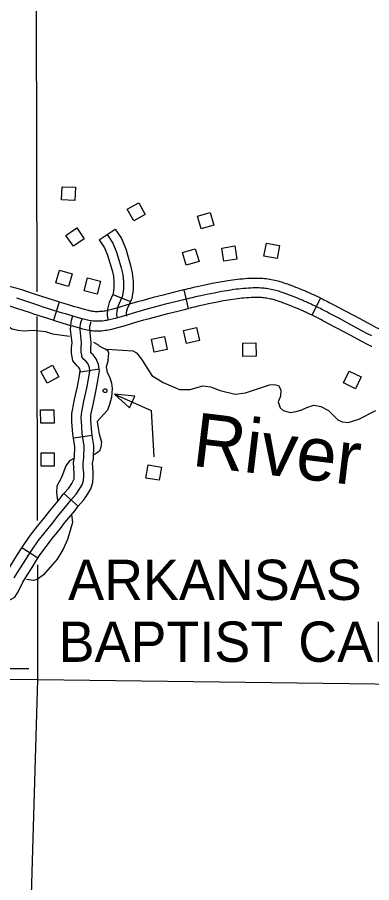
# Model space of a CAD drawing. Extents: x -19 to 366, y -4 to 359.
# Drawn here: x 137.366 to 137.894, y 192.721 to 194.009 of the extents above; entities that cross this region are included whole.
import ezdxf

# ---------------------------------------------------------------- set-up
doc = ezdxf.new("R2010")
doc.units = 0
for name, color, linetype in [('21', 7, 'Continuous'), ('60', 7, 'Continuous'), ('R_Axis Annot', 7, 'Continuous'), ('R_ROW', 7, 'Continuous'), ('R_ROW Annot', 7, 'Continuous'), ('R_Temp Easement', 7, 'Continuous'), ('Sheet Fence', 7, 'Continuous')]:
    doc.layers.add(name, color=color, linetype=linetype)

msp = doc.modelspace()

# ---------------------------------------------------------------- linework, layer by layer
at = {"layer": '21'}
for points in [[(137.4528, 193.7563), (137.452, 193.7366), (137.4322, 193.7374), (137.4331, 193.7571)], [(137.5395, 193.7062), (137.5299, 193.7234), (137.5472, 193.733), (137.5568, 193.7158)], [(137.6533, 193.7189), (137.6589, 193.7), (137.6399, 193.6944), (137.6343, 193.7133)], [(137.4548, 193.6958), (137.466, 193.6796), (137.4498, 193.6683), (137.4386, 193.6845)], [(137.6902, 193.6688), (137.6932, 193.6493), (137.6737, 193.6463), (137.6706, 193.6657)], [(137.7564, 193.6696), (137.7529, 193.6502), (137.7334, 193.6538), (137.737, 193.6732)], [(137.6312, 193.6648), (137.6368, 193.6459), (137.6178, 193.6403), (137.6122, 193.6592)], [(137.4234, 193.6141), (137.4291, 193.633), (137.448, 193.6272), (137.4423, 193.6084)], [(137.49, 193.6164), (137.485, 193.5973), (137.4659, 193.6022), (137.4708, 193.6213)], [(137.6375, 193.5283), (137.6183, 193.5237), (137.6137, 193.5429), (137.6329, 193.5476)], [(137.5699, 193.5108), (137.566, 193.5302), (137.5854, 193.5341), (137.5893, 193.5148)], [(137.702, 193.5043), (137.7017, 193.524), (137.7214, 193.5244), (137.7218, 193.5047)], [(137.4279, 193.4738), (137.4105, 193.4645), (137.4012, 193.482), (137.4185, 193.4913)], [(137.8782, 193.4741), (137.8697, 193.4563), (137.8518, 193.4648), (137.8604, 193.4826)], [(137.5332, 193.4278), (137.5411, 193.4454), (137.5108, 193.4484)], [(137.4012, 193.4049), (137.4009, 193.4246), (137.4206, 193.425), (137.421, 193.4052)], [(137.4016, 193.3411), (137.4016, 193.3608), (137.4213, 193.3608), (137.4213, 193.3411)], [(137.5578, 193.3233), (137.5612, 193.3427), (137.5807, 193.3393), (137.5773, 193.3199)]]:
    msp.add_lwpolyline(points, close=True, dxfattribs=at)
msp.add_lwpolyline([(137.5108, 193.4484), (137.5653, 193.424), (137.5693, 193.355)], dxfattribs=at)
msp.add_circle((137.4969, 193.4533), 0.00284, dxfattribs=at)
at = {"layer": '60'}
msp.add_line((137.2746, 193.0395), (137.3833, 193.0395), dxfattribs=at)
at = {"layer": 'R_Axis Annot'}
for points in [[(137.3958, 193.6004), (137.395, 194.0184)], [(137.3965, 193.2601), (137.3959, 193.5638)], [(137.3969, 193.0228), (137.3966, 193.1939)], [(137.3969, 193.0228), (137.0833, 193.0239)], [(137.3674, 192.0278), (137.3969, 193.0228)], [(138.4006, 193.0099), (137.3969, 193.0228)]]:
    msp.add_lwpolyline(points, dxfattribs=at)
at = {"layer": 'R_ROW'}
for p, q in [((137.6212, 193.5759), (137.6146, 193.6035)), ((137.8052, 193.5656), (137.8174, 193.5913)), ((137.8174, 193.5913), (137.8174, 193.5913)), ((137.4284, 193.5854), (137.42, 193.5582)), ((137.5174, 193.5773), (137.5174, 193.5773))]:
    msp.add_line(p, q, dxfattribs=at)
for points in [[(137.7159, 193.6205), (137.7134, 193.6204), (137.7093, 193.6202), (137.7053, 193.6199), (137.7014, 193.6196), (137.6977, 193.6192), (137.694, 193.6188), (137.6903, 193.6184), (137.6866, 193.6178), (137.6794, 193.6167), (137.6684, 193.615), (137.6564, 193.6127), (137.6452, 193.6105), (137.6362, 193.6085), (137.6284, 193.6068), (137.6233, 193.6055), (137.6202, 193.6048), (137.6169, 193.6041), (137.6146, 193.6035)], [(137.8174, 193.5913), (137.8171, 193.5914), (137.8114, 193.5941), (137.8095, 193.595), (137.8076, 193.5959), (137.8056, 193.5968), (137.8037, 193.5977), (137.8018, 193.5985), (137.7999, 193.5993), (137.7979, 193.6002), (137.796, 193.601), (137.7941, 193.6018), (137.7896, 193.6036), (137.7851, 193.6055), (137.783, 193.6063), (137.781, 193.6072), (137.779, 193.608), (137.7769, 193.6088), (137.7749, 193.6095), (137.7729, 193.6103), (137.7708, 193.6111), (137.7687, 193.6118), (137.7666, 193.6125), (137.7621, 193.614), (137.7598, 193.6148), (137.7573, 193.6156), (137.7547, 193.6163), (137.7521, 193.617), (137.7495, 193.6176), (137.7469, 193.6181), (137.7418, 193.619), (137.7394, 193.6194), (137.7369, 193.6198), (137.7343, 193.6201), (137.7317, 193.6203), (137.7292, 193.6204), (137.7266, 193.6205), (137.7169, 193.6205), (137.7159, 193.6205)], [(137.4284, 193.5854), (137.428, 193.5855), (137.4233, 193.587), (137.4186, 193.5885), (137.4138, 193.59), (137.4092, 193.5915), (137.4044, 193.593), (137.3997, 193.5945), (137.395, 193.5961), (137.3731, 193.6034), (137.3695, 193.6045), (137.3659, 193.6056), (137.3623, 193.6066), (137.3587, 193.6076), (137.355, 193.6085), (137.3513, 193.6093), (137.3477, 193.61), (137.344, 193.6107), (137.3402, 193.6114), (137.3365, 193.612), (137.3328, 193.6125), (137.3297, 193.6128)], [(137.8939, 193.5348), (137.8866, 193.5387), (137.8617, 193.552), (137.8456, 193.5606), (137.8299, 193.569), (137.8278, 193.5701), (137.8258, 193.5712), (137.8237, 193.5723), (137.8216, 193.5734), (137.8195, 193.5744), (137.8174, 193.5755), (137.8153, 193.5765), (137.8132, 193.5776), (137.811, 193.5786), (137.8053, 193.5813), (137.8035, 193.5822), (137.8016, 193.583), (137.7998, 193.5839), (137.798, 193.5847), (137.7961, 193.5855), (137.7943, 193.5863), (137.7924, 193.5871), (137.7906, 193.5879), (137.7887, 193.5886), (137.7841, 193.5905), (137.7796, 193.5924), (137.7777, 193.5932), (137.7757, 193.594), (137.7738, 193.5947), (137.7718, 193.5955), (137.7699, 193.5962), (137.7679, 193.597), (137.766, 193.5977), (137.764, 193.5984), (137.762, 193.5991), (137.7576, 193.6006), (137.7554, 193.6013), (137.7532, 193.602), (137.751, 193.6026), (137.7487, 193.6032), (137.7465, 193.6037), (137.7443, 193.6042), (137.7394, 193.605), (137.7373, 193.6054), (137.7351, 193.6057), (137.733, 193.6059), (137.7308, 193.6061), (137.7286, 193.6062), (137.7264, 193.6063), (137.7171, 193.6063), (137.714, 193.6062), (137.7102, 193.606), (137.7063, 193.6057), (137.7027, 193.6054), (137.6992, 193.6051), (137.6957, 193.6047), (137.6922, 193.6043), (137.6887, 193.6038), (137.6815, 193.6027), (137.6709, 193.601), (137.6591, 193.5988), (137.6481, 193.5966), (137.6393, 193.5946), (137.6316, 193.5929), (137.6265, 193.5917), (137.6234, 193.591), (137.6201, 193.5902), (137.6169, 193.5895), (137.6137, 193.5887), (137.6018, 193.5858), (137.5868, 193.582), (137.5721, 193.5782), (137.5554, 193.5735), (137.5508, 193.5723), (137.5386, 193.5688), (137.5241, 193.5645), (137.5121, 193.561), (137.5037, 193.5588), (137.5017, 193.5584), (137.4997, 193.558)], [(137.6146, 193.6035), (137.6136, 193.6033), (137.6103, 193.6025), (137.5983, 193.5995), (137.5833, 193.5958), (137.5684, 193.5919), (137.5516, 193.5872), (137.5469, 193.586), (137.5347, 193.5825), (137.5201, 193.5781), (137.5174, 193.5773)], [(137.4627, 193.5604), (137.4573, 193.562), (137.4525, 193.5633), (137.4477, 193.5647), (137.4429, 193.5662), (137.4381, 193.5676), (137.4334, 193.569), (137.4286, 193.5705), (137.4238, 193.5719), (137.419, 193.5734), (137.4143, 193.5749), (137.4095, 193.5764), (137.4048, 193.5779), (137.4, 193.5795), (137.3953, 193.581), (137.3906, 193.5826), (137.3687, 193.5899), (137.3654, 193.5909)], [(137.7169, 193.5921), (137.7146, 193.592), (137.711, 193.5918), (137.7074, 193.5916), (137.7039, 193.5913), (137.7006, 193.591), (137.6973, 193.5906), (137.6941, 193.5902), (137.6908, 193.5897), (137.6837, 193.5886), (137.6733, 193.587), (137.6618, 193.5848), (137.651, 193.5827), (137.6423, 193.5808), (137.6348, 193.5791), (137.6298, 193.5779), (137.6266, 193.5772), (137.6234, 193.5764), (137.6212, 193.5759)], [(137.8052, 193.5656), (137.805, 193.5657), (137.7992, 193.5685), (137.7974, 193.5693), (137.7957, 193.5701), (137.7939, 193.5709), (137.7922, 193.5717), (137.7904, 193.5725), (137.7887, 193.5732), (137.7869, 193.574), (137.7852, 193.5747), (137.7833, 193.5755), (137.7787, 193.5774), (137.7742, 193.5793), (137.7723, 193.58), (137.7704, 193.5808), (137.7686, 193.5815), (137.7668, 193.5822), (137.7649, 193.5829), (137.763, 193.5836), (137.7612, 193.5843), (137.7593, 193.585), (137.7574, 193.5856), (137.753, 193.5871), (137.751, 193.5878), (137.7491, 193.5884), (137.7473, 193.5889), (137.7454, 193.5894), (137.7435, 193.5898), (137.7416, 193.5902), (137.7371, 193.591), (137.7352, 193.5913), (137.7334, 193.5916), (137.7316, 193.5918), (137.7298, 193.5919), (137.7281, 193.592), (137.7262, 193.5921), (137.7174, 193.5921), (137.7169, 193.5921)], [(137.8174, 193.5913), (137.8193, 193.5904), (137.8215, 193.5893), (137.8237, 193.5882), (137.8259, 193.5871), (137.8281, 193.586), (137.8302, 193.5849), (137.8324, 193.5838), (137.8346, 193.5826), (137.8366, 193.5815), (137.8523, 193.5731), (137.8684, 193.5646), (137.8933, 193.5512), (137.9003, 193.5474), (137.903, 193.5462), (137.9058, 193.5448), (137.9059, 193.5448)], [(137.42, 193.5582), (137.4196, 193.5584), (137.4148, 193.5599), (137.41, 193.5614), (137.4052, 193.5629), (137.4004, 193.5644), (137.3956, 193.566), (137.3909, 193.5675), (137.3861, 193.5691), (137.3643, 193.5764), (137.3612, 193.5774), (137.358, 193.5783), (137.3549, 193.5792), (137.3517, 193.58), (137.3485, 193.5808), (137.3453, 193.5815), (137.3421, 193.5822), (137.3389, 193.5828), (137.3357, 193.5833), (137.3324, 193.5838), (137.3293, 193.5843), (137.3265, 193.5846)], [(137.5174, 193.5773), (137.5084, 193.5747), (137.5004, 193.5726), (137.4988, 193.5723), (137.4972, 193.572), (137.4956, 193.5717), (137.4937, 193.5715), (137.4915, 193.5713), (137.4893, 193.5711), (137.4871, 193.5709), (137.4852, 193.5709), (137.4838, 193.5709), (137.4821, 193.571), (137.4804, 193.5711), (137.4787, 193.5713), (137.477, 193.5716), (137.4755, 193.5718), (137.4704, 193.573), (137.4665, 193.5741), (137.4612, 193.5756), (137.4565, 193.577), (137.4517, 193.5784), (137.447, 193.5798), (137.4422, 193.5812), (137.4375, 193.5826), (137.4327, 193.5841), (137.4284, 193.5854)], [(137.5253, 193.55), (137.5282, 193.5508), (137.5426, 193.5552), (137.5546, 193.5586), (137.5591, 193.5598), (137.5758, 193.5644), (137.5903, 193.5682), (137.6052, 193.572), (137.6171, 193.5749), (137.6203, 193.5757), (137.6212, 193.5759)], [(137.8937, 193.5191), (137.8936, 193.5192), (137.8906, 193.5206), (137.8875, 193.5221), (137.8799, 193.5261), (137.855, 193.5395), (137.8389, 193.5481), (137.8232, 193.5565), (137.8211, 193.5576), (137.8191, 193.5586), (137.8171, 193.5597), (137.8151, 193.5607), (137.8131, 193.5618), (137.8111, 193.5628), (137.809, 193.5638), (137.807, 193.5648), (137.8052, 193.5656)], [(137.42, 193.5582), (137.4244, 193.5569), (137.4293, 193.5554), (137.4341, 193.554), (137.4389, 193.5525), (137.4437, 193.5511), (137.4485, 193.5497), (137.4534, 193.5483), (137.4588, 193.5468), (137.4634, 193.5455), (137.47, 193.544), (137.4726, 193.5435), (137.4751, 193.5432), (137.4776, 193.5429), (137.4801, 193.5427), (137.4826, 193.5425), (137.4853, 193.5424), (137.4885, 193.5426), (137.4914, 193.5427), (137.4942, 193.543), (137.4971, 193.5433), (137.4997, 193.5436), (137.5021, 193.544), (137.5046, 193.5445), (137.5069, 193.545), (137.5158, 193.5473), (137.5253, 193.55)], [(137.4997, 193.558), (137.4977, 193.5577), (137.4954, 193.5574), (137.4929, 193.5571), (137.4904, 193.5569), (137.4878, 193.5567), (137.4853, 193.5567), (137.4832, 193.5567), (137.4811, 193.5568), (137.479, 193.557), (137.4769, 193.5572), (137.4748, 193.5575), (137.4728, 193.5579), (137.4669, 193.5592), (137.4627, 193.5604)]]:
    msp.add_lwpolyline(points, dxfattribs=at)
at = {"layer": 'R_ROW Annot'}
for p, q in [((137.4882, 193.6781), (137.5118, 193.6939)), ((137.5083, 193.5968), (137.5345, 193.5859)), ((137.4883, 193.4855), (137.4602, 193.4809)), ((137.4779, 193.3867), (137.4498, 193.3825)), ((137.4568, 193.2813), (137.4356, 193.3002)), ((137.3968, 193.2038), (137.3732, 193.2196))]:
    msp.add_line(p, q, dxfattribs=at)
for points in [[(137.5118, 193.6939), (137.5212, 193.6798), (137.5276, 193.6645), (137.5346, 193.6398), (137.5374, 193.6286), (137.5385, 193.6161), (137.5385, 193.604), (137.5365, 193.5907), (137.5345, 193.5859)], [(137.5, 193.686), (137.5086, 193.673), (137.5141, 193.6598), (137.5209, 193.6361), (137.5234, 193.6262), (137.5243, 193.6155), (137.5243, 193.605), (137.5227, 193.5945), (137.5166, 193.5797), (137.5144, 193.5724), (137.5141, 193.5665), (137.515, 193.5618)], [(137.4882, 193.6781), (137.496, 193.6663), (137.5007, 193.6551), (137.5072, 193.6324), (137.5093, 193.6239), (137.5101, 193.6149), (137.5101, 193.606), (137.5089, 193.5984), (137.5083, 193.5968)], [(137.5083, 193.5968), (137.5032, 193.5845), (137.5003, 193.5748), (137.4999, 193.5656), (137.501, 193.5593)], [(137.5345, 193.5859), (137.53, 193.575), (137.5285, 193.57), (137.5284, 193.5674), (137.529, 193.5644)], [(137.4602, 193.4809), (137.4597, 193.484), (137.4586, 193.4866), (137.4577, 193.4879), (137.4552, 193.4902), (137.4488, 193.4976), (137.448, 193.504), (137.4471, 193.5093), (137.4471, 193.5176), (137.4477, 193.5244), (137.4456, 193.5438), (137.4457, 193.5504), (137.447, 193.5583), (137.4491, 193.5648)], [(137.3618, 193.1749), (137.3691, 193.1865), (137.3764, 193.1978), (137.383, 193.2086), (137.3878, 193.2158), (137.3975, 193.2297), (137.4075, 193.2427), (137.4191, 193.2567), (137.426, 193.2659), (137.4407, 193.2835), (137.4457, 193.2902), (137.454, 193.2995), (137.4593, 193.3075), (137.4626, 193.3131), (137.4647, 193.3194), (137.4652, 193.3259), (137.4651, 193.3303), (137.4645, 193.3397), (137.4641, 193.3457), (137.4655, 193.3532), (137.4659, 193.3707), (137.463, 193.39), (137.4616, 193.4079), (137.4614, 193.4129), (137.4617, 193.4178), (137.4623, 193.4217), (137.4655, 193.4375), (137.4696, 193.4571), (137.4725, 193.4736), (137.4743, 193.4829), (137.4735, 193.488), (137.471, 193.4937), (137.4684, 193.4973), (137.4655, 193.5), (137.4624, 193.5036), (137.4621, 193.5062), (137.4613, 193.5105), (137.4613, 193.517), (137.4619, 193.5246), (137.4598, 193.5445), (137.4599, 193.5491), (137.4609, 193.5549), (137.4627, 193.5604)], [(137.4883, 193.4855), (137.4872, 193.4921), (137.4834, 193.5008), (137.4791, 193.5068), (137.4759, 193.5098), (137.4755, 193.5118), (137.4755, 193.5164), (137.4762, 193.5247), (137.474, 193.5451), (137.4741, 193.5477), (137.4747, 193.5515), (137.4762, 193.556)], [(137.4498, 193.3825), (137.4489, 193.3884), (137.4474, 193.4071), (137.4472, 193.4132), (137.4476, 193.4193), (137.4483, 193.4242), (137.4516, 193.4404), (137.4556, 193.4598), (137.4586, 193.4762), (137.4599, 193.4831), (137.4602, 193.4809)], [(137.4779, 193.3867), (137.4772, 193.3916), (137.4758, 193.4086), (137.4756, 193.4127), (137.4759, 193.4163), (137.4763, 193.4193), (137.4795, 193.4347), (137.4835, 193.4544), (137.4865, 193.471), (137.4887, 193.4827), (137.4883, 193.4855)], [(137.4568, 193.2813), (137.4653, 193.2908), (137.4713, 193.3), (137.4756, 193.3072), (137.4787, 193.3166), (137.4794, 193.3256), (137.4793, 193.3309), (137.4787, 193.3406), (137.4784, 193.3449), (137.4797, 193.3517), (137.4802, 193.3716), (137.4779, 193.3867)], [(137.4356, 193.3002), (137.4427, 193.3081), (137.4472, 193.315), (137.4496, 193.319), (137.4507, 193.3223), (137.451, 193.3262), (137.4509, 193.3297), (137.4504, 193.3389), (137.4499, 193.3466), (137.4514, 193.3547), (137.4517, 193.3698), (137.4498, 193.3825)], [(137.3732, 193.2196), (137.376, 193.2238), (137.3861, 193.2381), (137.3964, 193.2516), (137.4079, 193.2655), (137.4148, 193.2747), (137.4295, 193.2923), (137.4347, 193.2992), (137.4356, 193.3002)], [(137.3968, 193.2038), (137.3995, 193.2078), (137.409, 193.2213), (137.4186, 193.2339), (137.4303, 193.2479), (137.4371, 193.2571), (137.4518, 193.2746), (137.4567, 193.2812), (137.4568, 193.2813)], [(137.3143, 193.1518), (137.3425, 193.1672), (137.3426, 193.1674), (137.3493, 193.1818), (137.3571, 193.1941), (137.3643, 193.2053), (137.371, 193.2163), (137.3732, 193.2196)], [(137.3278, 193.1269), (137.3624, 193.1457), (137.3676, 193.1536), (137.3743, 193.1681), (137.3811, 193.1789), (137.3884, 193.1903), (137.395, 193.201), (137.3968, 193.2038)]]:
    msp.add_lwpolyline(points, dxfattribs=at)
at = {"layer": 'R_Temp Easement'}
for points in [[(137.3172, 193.579), (137.335, 193.5725), (137.3419, 193.5669), (137.3467, 193.556), (137.3505, 193.5503), (137.3586, 193.5455), (137.3669, 193.5434), (137.3767, 193.5424), (137.39, 193.5434), (137.4081, 193.5415), (137.4188, 193.5382), (137.4441, 193.5345)], [(137.4799, 193.5258), (137.4863, 193.5219), (137.4886, 193.5197), (137.4974, 193.5153), (137.5072, 193.5147), (137.5382, 193.5126), (137.5436, 193.5096), (137.5513, 193.5003), (137.5665, 193.4762), (137.5833, 193.4655), (137.6076, 193.4549), (137.6235, 193.4552), (137.6423, 193.4608), (137.654, 193.4591), (137.6681, 193.4537), (137.6905, 193.448), (137.706, 193.4501), (137.7417, 193.4621), (137.7492, 193.4626), (137.7549, 193.4612), (137.7584, 193.4544), (137.7578, 193.445), (137.7546, 193.4369), (137.7574, 193.4279), (137.762, 193.4238), (137.7722, 193.4209), (137.7813, 193.4222), (137.7899, 193.425), (137.797, 193.4285), (137.8076, 193.4318), (137.8182, 193.43), (137.8292, 193.4238), (137.8435, 193.41), (137.8499, 193.4071), (137.8586, 193.4061), (137.8748, 193.4109), (137.8999, 193.4238)], [(137.5016, 193.4993), (137.5025, 193.5094), (137.5014, 193.5123), (137.4974, 193.5153)], [(137.5016, 193.4993), (137.4986, 193.4886), (137.5001, 193.4806), (137.5039, 193.473), (137.5066, 193.4647), (137.5074, 193.4567), (137.5063, 193.4438), (137.5037, 193.4328), (137.5004, 193.4241), (137.4853, 193.4077), (137.4861, 193.4005), (137.488, 193.3884), (137.4915, 193.3774), (137.4908, 193.3694), (137.4885, 193.3634), (137.4798, 193.3573)], [(137.4513, 193.3528), (137.444, 193.349), (137.4383, 193.3417), (137.4318, 193.3239), (137.4251, 193.3113), (137.4247, 193.3015), (137.4259, 193.29)], [(137.447, 193.2695), (137.4482, 193.2571), (137.4412, 193.232), (137.4344, 193.2172), (137.4254, 193.2027), (137.4051, 193.1791), (137.3957, 193.1723), (137.3904, 193.1707), (137.3797, 193.1721)]]:
    msp.add_lwpolyline(points, dxfattribs=at)
at = {"layer": 'Sheet Fence'}
for points in [[(139.4406, 1.5315), (139.2511, 10.1473), (139.0608, 18.7633), (138.8699, 27.3793), (138.6784, 35.9956), (138.4861, 44.6119), (138.2932, 53.2285), (138.0997, 61.8451), (137.9055, 70.4619), (137.7106, 79.0789), (137.5151, 87.6959), (137.319, 96.3132), (137.1221, 104.9306), (136.9247, 113.5481), (136.7265, 122.1658), (136.5278, 130.7836), (136.3283, 139.4016), (136.1282, 148.0197), (135.9275, 156.6379), (135.7261, 165.2564), (135.5241, 173.8749), (135.3214, 182.4936), (135.1181, 191.1125), (134.9141, 199.7315), (134.7095, 208.3506), (134.5043, 216.9699), (134.2984, 225.5894), (134.0919, 234.209), (133.8847, 242.8288), (133.6769, 251.4487), (133.4685, 260.0687), (133.2594, 268.6889), (133.0497, 277.3093), (132.8393, 285.9298), (132.6283, 294.5504), (132.4167, 303.1713), (132.2044, 311.7922), (131.9916, 320.4133), (131.778, 329.0346), (131.5639, 337.656), (131.3491, 346.2776)], [(0, 189.5162), (7.1121, 189.5206), (14.2243, 189.5339), (21.3364, 189.556), (28.4484, 189.5869), (35.5605, 189.6267), (42.6725, 189.6754), (49.7844, 189.7329), (56.8962, 189.7992), (64.0079, 189.8744), (71.1196, 189.9584), (78.2311, 190.0512), (85.3425, 190.1529), (92.4538, 190.2635), (99.5649, 190.3829), (106.6759, 190.5111), (113.7867, 190.6482), (120.8974, 190.7941), (128.0078, 190.9489), (135.1181, 191.1125), (142.2282, 191.2849), (149.338, 191.4662), (156.4476, 191.6563), (163.5569, 191.8553), (170.666, 192.0631), (177.7749, 192.2798), (184.8835, 192.5053), (191.9917, 192.7396), (199.0997, 192.9828), (206.2074, 193.2348), (213.3147, 193.4956), (220.4218, 193.7653), (227.5285, 194.0438), (234.6348, 194.3312), (241.7408, 194.6274), (248.8464, 194.9324), (255.9516, 195.2463), (263.0564, 195.569), (270.1608, 195.9005), (277.2648, 196.2409), (284.3683, 196.5901), (291.4715, 196.9481), (298.5741, 197.315), (305.6763, 197.6907), (312.7781, 198.0753), (319.8793, 198.4686), (326.9801, 198.8708), (334.0804, 199.2818), (341.1801, 199.7017)]]:
    msp.add_spline(points, degree=3, dxfattribs=at)

# ---------------------------------------------------------------- texts
at = {"layer": '60'}
for s, p in [('ARKANSAS', (137.4419, 193.1417)), ('BAPTIST CAMP', (137.4277, 193.0496))]:
    msp.add_text(s, height=0.06, dxfattribs=at).set_placement(p)
at = {"layer": 'R_Temp Easement'}
msp.add_text('River', height=0.08, rotation=353.1919, dxfattribs=at).set_placement((137.6248, 193.3417))

doc.saveas('drawing.dxf')
